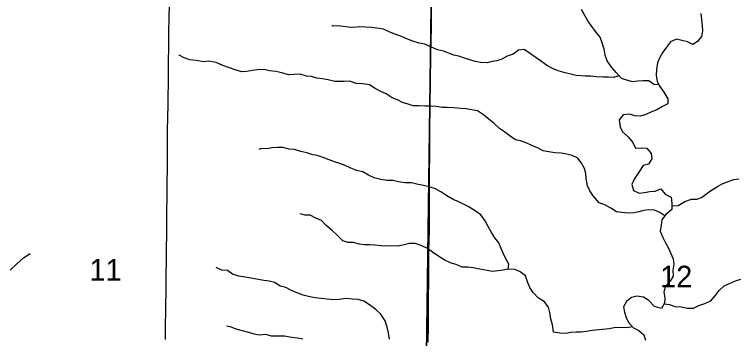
# Model space of a CAD drawing. Extents: x 1874609 to 2204689, y 815661 to 1281160.
# Drawn here: x 2036147 to 2043513, y 1048135 to 1051437 of the extents above; entities that cross this region are included whole.
import ezdxf

# ---------------------------------------------------------------- set-up
doc = ezdxf.new("R2010")
doc.units = 0
for name, color, linetype in [('GM_X_Minor_River', 7, 'Continuous'), ('GM_X_Section', 7, 'Continuous'), ('GM_X_Section_Text', 7, 'Continuous'), ('GM_X_Township_Road', 7, 'Continuous')]:
    doc.layers.add(name, color=color, linetype=linetype)

msp = doc.modelspace()

# ---------------------------------------------------------------- linework, layer by layer
at = {"layer": 'GM_X_Minor_River'}
for points in [[(2042720.8, 1050721.2), (2042670.5, 1050723.7), (2042616.9, 1050762.2), (2042558.9, 1050760.8), (2042506.9, 1050757.3), (2042452.8, 1050751.8), (2042395, 1050766.4), (2042339.1, 1050785), (2042285.7, 1050845.6), (2042240.1, 1050898.1), (2042192.7, 1050964.7), (2042171.2, 1051021), (2042161.7, 1051083.2), (2042142.3, 1051147.5), (2042120.8, 1051205.8), (2042075.3, 1051264.4), (2042029.8, 1051322.9), (2041996.2, 1051373.3), (2041964.7, 1051427.8), (2041931.2, 1051488.2)], [(2043148.5, 1051448.3), (2043155.9, 1051386.1), (2043161.4, 1051322), (2043165, 1051271.8), (2043154.5, 1051213.8), (2043116.1, 1051162.1), (2043065.8, 1051132.6), (2043012.1, 1051157.1), (2042956.2, 1051171.7), (2042900.3, 1051184.2), (2042840.1, 1051158.8), (2042797.7, 1051105.1), (2042761.2, 1051051.4), (2042730.8, 1050999.6), (2042706.4, 1050943.7), (2042697.8, 1050877.7), (2042693.3, 1050819.6), (2042702.8, 1050755.4), (2042730.3, 1050703.1), (2042771.8, 1050644.6), (2042811.2, 1050578), (2042810.8, 1050528), (2042758.6, 1050498.4), (2042698.3, 1050466.9), (2042640.1, 1050441.5), (2042587.9, 1050417.9), (2042531.8, 1050400.4), (2042475.9, 1050405), (2042420, 1050419.6)], [(2042316.3, 1050810.9), (2042259.2, 1050793.8), (2042205.3, 1050798.3), (2042153.3, 1050798.8), (2042079.4, 1050801.5), (2042025.5, 1050808.1), (2041971.5, 1050808.6), (2041875.6, 1050815.5), (2041823.7, 1050830.1), (2041763.8, 1050840.7), (2041694, 1050863.4), (2041636.3, 1050888), (2041576.5, 1050916.6), (2041522.9, 1050957.2), (2041469.2, 1050995.8), (2041409.6, 1051034.4), (2041348, 1051079.1), (2041289.9, 1051071.7), (2041233.6, 1051032.1), (2041173.5, 1051010.7), (2041119.3, 1050983.2), (2041069.1, 1050965.6), (2041019.1, 1050958.1), (2040969, 1050944.6), (2040901, 1050947.2), (2040845.1, 1050957.8), (2040737.5, 1050990.9), (2040681.7, 1051013.5), (2040627.8, 1051022), (2040524.1, 1051063.1), (2040462.3, 1051077.7), (2040402.5, 1051102.3), (2040332.8, 1051133.1), (2040274.9, 1051145.6), (2040211.1, 1051166.3), (2040157.3, 1051186.9), (2040087.6, 1051215.6), (2040035.8, 1051234.1), (2039976, 1051256.7), (2039912.3, 1051287.4), (2039844.4, 1051296.1), (2039790.5, 1051304.6), (2039730.5, 1051309.2), (2039668.5, 1051309.8), (2039610.5, 1051304.4), (2039552.6, 1051308.9), (2039498.7, 1051315.5), (2039446.7, 1051320), (2039394.7, 1051318.5), (2039384.8, 1051328.6)], [(2042781.8, 1049383.6), (2042729.5, 1049420.8), (2042675.7, 1049443.4), (2042619.7, 1049445.9), (2042567.7, 1049440.4), (2042517.6, 1049424.9), (2042467.5, 1049417.3), (2042409.5, 1049413.9), (2042343.6, 1049418.6), (2042287.7, 1049427.1), (2042232, 1049463.7), (2042176.3, 1049494.3), (2042112.5, 1049519), (2042049.1, 1049589.7), (2042017.6, 1049640.1), (2041992, 1049692.4), (2041978.7, 1049766.7), (2041975.1, 1049816.8), (2041963.5, 1049867), (2041930, 1049921.4), (2041894.4, 1049971.9), (2041834.7, 1049998.5), (2041782.8, 1050013), (2041724.9, 1050023.6), (2041659, 1050026.3), (2041597.1, 1050038.9), (2041541.2, 1050047.4), (2041483.5, 1050078.1), (2041425.7, 1050100.7), (2041367.9, 1050129.3), (2041310.1, 1050147.9), (2041258.2, 1050160.4), (2041202.6, 1050197), (2041147, 1050239.6), (2041095.3, 1050276.2), (2041041.7, 1050326.8), (2040990.1, 1050367.3), (2040930.5, 1050414), (2040870.9, 1050454.7), (2040809, 1050465.3), (2040755.1, 1050473.8), (2040701.1, 1050478.3), (2040629.2, 1050485.1), (2040561.3, 1050487.7), (2040509.3, 1050490.2), (2040449.4, 1050498.8), (2040397.4, 1050501.3), (2040337.5, 1050501.9), (2040271.5, 1050506.6), (2040213.6, 1050507.1), (2040161.7, 1050521.6), (2040105.9, 1050540.2), (2040054.1, 1050566.8), (2040000.3, 1050587.3), (2039938.7, 1050630), (2039884.9, 1050652.6), (2039827.2, 1050681.2), (2039767.5, 1050719.8), (2039701.6, 1050730.5), (2039633.7, 1050735.1), (2039567.9, 1050755.8), (2039509.9, 1050752.4), (2039413.9, 1050753.3), (2039346.1, 1050772), (2039290.2, 1050780.6), (2039230.3, 1050789.1), (2039178.5, 1050805.7), (2039126.5, 1050808.2), (2039060.7, 1050828.9), (2038996.7, 1050825.5), (2038942.7, 1050822), (2038874.9, 1050840.7), (2038813, 1050857.3), (2038747.1, 1050864), (2038693.2, 1050876.5), (2038627.2, 1050873.1), (2038571.2, 1050867.7), (2038517.1, 1050856.2), (2038465.1, 1050852.7), (2038399.3, 1050871.3), (2038341.5, 1050894), (2038273.7, 1050918.6), (2038204, 1050947.4), (2038128.1, 1050962.1), (2038078.1, 1050954.6), (2038000.2, 1050967.4), (2037936.3, 1050976), (2037878.5, 1050996.6), (2037826.8, 1051023.2), (2037828.8, 1051027.2)], [(2042420, 1050419.6), (2042358, 1050414.1), (2042315.6, 1050362.5), (2042327, 1050292.2), (2042348.5, 1050239.9), (2042408.1, 1050189.3), (2042455.6, 1050132.7), (2042483.1, 1050074.3), (2042545.1, 1050077.8), (2042599, 1050075.2), (2042642.6, 1050020.7), (2042650.1, 1049966.5), (2042615.7, 1049912.8), (2042559.5, 1049897.3), (2042523.1, 1049841.6), (2042468.4, 1049759.9), (2042446, 1049706.1), (2042463.4, 1049643.8), (2042519.2, 1049615.2), (2042569.2, 1049622.7), (2042629.3, 1049632.1), (2042683.3, 1049637.6), (2042741.5, 1049659.1), (2042785, 1049606.6), (2042844.7, 1049574), (2042852.2, 1049511.8), (2042853.7, 1049449.7), (2042793.2, 1049398.2), (2042750.8, 1049344.5), (2042744.3, 1049290.4), (2042733.8, 1049228.4), (2042761.3, 1049164.1), (2042786.8, 1049109.7), (2042820.3, 1049057.3), (2042839.9, 1049007), (2042867.4, 1048946.6), (2042872.9, 1048892.5), (2042862.4, 1048830.5), (2042867.9, 1048770.3), (2042837.5, 1048718.5), (2042785, 1048664.9), (2042772.5, 1048607), (2042780, 1048546.8), (2042777.6, 1048494.7), (2042749.2, 1048440.9), (2042675.4, 1048461.6), (2042619.9, 1048522.3), (2042564.2, 1048554.9), (2042496.3, 1048565.6), (2042442.2, 1048552.1), (2042391.9, 1048512.5), (2042361.4, 1048456.7), (2042371, 1048402.5), (2042388.5, 1048350.2), (2042412.1, 1048299.9), (2042461.6, 1048245.4), (2042517.3, 1048216.8), (2042568.9, 1048172.2), (2042584.5, 1048119.9)], [(2041183.8, 1048840.7), (2041189.5, 1048892.8), (2041156.1, 1048953.3), (2041132.5, 1049003.6), (2041112.9, 1049053.9), (2041087.4, 1049110.2), (2041045.9, 1049160.7), (2041012.4, 1049217.1), (2040980.9, 1049277.5), (2040949.4, 1049335.9), (2040903.9, 1049396.5), (2040848.3, 1049437.1), (2040776.7, 1049481.9), (2040681.1, 1049528.9), (2040621.3, 1049551.5), (2040557.7, 1049588.2), (2040498, 1049628.8), (2040442.3, 1049659.4), (2040378.5, 1049680.1), (2040320.6, 1049692.7), (2040264.8, 1049705.2), (2040198.9, 1049719.9), (2040128.9, 1049720.6), (2040065, 1049731.2), (2040007.2, 1049743.8), (2039947.2, 1049744.4), (2039883.3, 1049755), (2039815.5, 1049773.7), (2039759.7, 1049800.3), (2039700, 1049832.9), (2039636.2, 1049847.6), (2039572.4, 1049874.2), (2039520.7, 1049898.8), (2039466.8, 1049919.3), (2039411, 1049933.9), (2039357.2, 1049954.5), (2039297.4, 1049979.1), (2039235.6, 1049999.7), (2039179.7, 1050010.3), (2039127.9, 1050026.8), (2039068, 1050039.4), (2039002.2, 1050062.1), (2038950.3, 1050064.6), (2038886.4, 1050081.2), (2038830.5, 1050081.8), (2038772.4, 1050078.3), (2038720.4, 1050068.8), (2038668.4, 1050071.3), (2038638.3, 1050061.6)], [(2042852.8, 1049486.6), (2042918, 1049489.1), (2042984.3, 1049532.5), (2043052.5, 1049553.9), (2043106.4, 1049553.4), (2043156.6, 1049570.9), (2043208.9, 1049612.5), (2043259.2, 1049648.1), (2043317.5, 1049685.6), (2043367.7, 1049711.1), (2043427.9, 1049734.6), (2043486, 1049754.1), (2043538, 1049761.6)], [(2042452.6, 1048255.3), (2042389.6, 1048244), (2042335.7, 1048246.6), (2042265.7, 1048243.3), (2042213.6, 1048233.7), (2042109.5, 1048222.7), (2042039.5, 1048215.4), (2041981.4, 1048205.9), (2041929.4, 1048198.4), (2041875.4, 1048199), (2041821.4, 1048195.5), (2041771.4, 1048185.9), (2041709.4, 1048188.5), (2041645.5, 1048201.2), (2041634.1, 1048273.4), (2041618.7, 1048333.7), (2041609.2, 1048401.9), (2041595.7, 1048456.1), (2041552.2, 1048512.6), (2041494.5, 1048547.3), (2041437, 1048603.9), (2041405.5, 1048656.3), (2041380, 1048712.7), (2041360.5, 1048773), (2041306.8, 1048815.6), (2041253.1, 1048838.1), (2041181.1, 1048840.8), (2041131, 1048831.3), (2041077, 1048823.8), (2041025, 1048818.3), (2040969.1, 1048828.9), (2040893.2, 1048841.6), (2040827.3, 1048854.3), (2040771.4, 1048860.8), (2040715.5, 1048863.4), (2040653.7, 1048888), (2040601.8, 1048902.6), (2040532.1, 1048935.3), (2040474.5, 1048971.9), (2040412.9, 1049014.6), (2040361.2, 1049051.1), (2040297.5, 1049083.8), (2040233.7, 1049102.5), (2040177.7, 1049103), (2040107.6, 1049087.7), (2040051.5, 1049076.2), (2039991.5, 1049078.8), (2039935.5, 1049075.3), (2039883.6, 1049079.8), (2039827.7, 1049086.4), (2039769.7, 1049090.9), (2039717.7, 1049089.4), (2039665.8, 1049096), (2039606, 1049112.6), (2039552, 1049115.1), (2039496.2, 1049131.7), (2039438.7, 1049188.3), (2039387.1, 1049234.9), (2039327.6, 1049287.6), (2039278, 1049338.1), (2039222.2, 1049362.7), (2039162.5, 1049393.4), (2039108.5, 1049391.9), (2039060.6, 1049404.4)], [(2036104.5, 1048830.9), (2036170.2, 1048897.7), (2036239.9, 1048956.4), (2036305.7, 1049003.1)], [(2039973.5, 1048127.3), (2039964.1, 1048193.5), (2039950.6, 1048249.7), (2039927.1, 1048316.1), (2039885.7, 1048382.6), (2039834.1, 1048431.2), (2039768.6, 1048479.9), (2039710.9, 1048514.5), (2039653, 1048531.1), (2039593.1, 1048535.7), (2039527.2, 1048542.3), (2039461.1, 1048533), (2039405.1, 1048529.5), (2039337.2, 1048536.2), (2039277.3, 1048542.8), (2039215.4, 1048551.4), (2039161.5, 1048559.9), (2039091.6, 1048578.6), (2039037.8, 1048597.2), (2038972.1, 1048623.9), (2038916.3, 1048654.5), (2038858.5, 1048669.1), (2038804.8, 1048707.6), (2038745, 1048720.2), (2038691, 1048726.8), (2038615.2, 1048739.5), (2038499.4, 1048758.7), (2038437.5, 1048771.3), (2038371.7, 1048790), (2038320, 1048826.6), (2038264.1, 1048833.1), (2038210.3, 1048855.7), (2038206.3, 1048859.7)], [(2042774.4, 1048488.6), (2042827.5, 1048482.2), (2042883.3, 1048461.6), (2042949.2, 1048459), (2043013.1, 1048444.3), (2043075.1, 1048443.8), (2043129.3, 1048473.3), (2043189.4, 1048490.7), (2043249.6, 1048520.2), (2043294.1, 1048571.8), (2043336.5, 1048625.5), (2043386.9, 1048673.1), (2043441.1, 1048696.6), (2043503.3, 1048724.1), (2043557.4, 1048741.6)], [(2039089.8, 1048127.9), (2039033.9, 1048138.4), (2038976, 1048147), (2038900.2, 1048159.8), (2038834.2, 1048158.4), (2038770.2, 1048159), (2038712.4, 1048175.6), (2038644.4, 1048170.2), (2038592.5, 1048180.8), (2038536.6, 1048197.3), (2038474.8, 1048212), (2038409, 1048230.6), (2038351.2, 1048253.2), (2038309.2, 1048259.7)]]:
    msp.add_lwpolyline(points, dxfattribs=at)
at = {"layer": 'GM_X_Section'}
for points in [[(2035069.6, 1051590.9), (2040397.9, 1051519.1), (2040325.7, 1046200.1), (2035027.7, 1046279.9)], [(2045458.8, 1051528.7), (2045434.8, 1046142), (2040325.7, 1046200.1), (2040397.9, 1051519.1)]]:
    msp.add_lwpolyline(points, close=True, dxfattribs=at)
at = {"layer": 'GM_X_Township_Road'}
for points in [[(2037687.3, 1048123.8), (2037688.7, 1048255.1), (2037691.1, 1048431.9), (2037694, 1048649.1), (2037695.2, 1048780.4), (2037697, 1048928.2), (2037698.2, 1049026.8), (2037701.6, 1049223.8), (2037701.8, 1049387.9), (2037703, 1049453.6), (2037704.9, 1049552), (2037705.7, 1049568.3), (2037706, 1049584.7), (2037706.2, 1049666.8), (2037705.5, 1049732.3), (2037707.2, 1049863.6), (2037708.4, 1050044.3), (2037709.9, 1050257.6), (2037713.8, 1050520.1), (2037716.6, 1050569.3), (2037718.6, 1050766.3), (2037720.1, 1050996.1), (2037721.2, 1051061.7), (2037722.8, 1051143.8), (2037723.2, 1051275.1), (2037723.6, 1051389.9), (2037727.3, 1051553.8)], [(2040368.3, 1048098.4), (2040370.6, 1048262.2), (2040371.9, 1048459), (2040372.3, 1048541), (2040374.6, 1048721.4), (2040375.4, 1048852.5), (2040375.6, 1048983.4), (2040374.9, 1049049), (2040376, 1049114.7), (2040379.7, 1049262.2), (2040380.2, 1049343.9), (2040379.8, 1049507.6), (2040379.9, 1049622.5), (2040379.6, 1049786.5), (2040382.7, 1050048.9), (2040383.1, 1050180.2), (2040383.6, 1050245.8), (2040384.4, 1050393.3), (2040385.4, 1050524.6), (2040387.7, 1050639.4), (2040389.3, 1050754), (2040390, 1050836.1), (2040391.8, 1050951), (2040399.2, 1051164.2), (2040399.9, 1051311.8), (2040400.1, 1051459.6)]]:
    msp.add_lwpolyline(points, dxfattribs=at)

# ---------------------------------------------------------------- texts
at = {"layer": 'GM_X_Section_Text'}
for s, p in [('11', (2036911.9, 1048724.4)), ('12', (2042733.1, 1048655.7))]:
    msp.add_text(s, height=221, rotation=0.00001, dxfattribs=at).set_placement(p)

doc.saveas('drawing.dxf')
